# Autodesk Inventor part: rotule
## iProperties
Shininess: 64.0
Length Units: 11269
Angle Units: 11279
Time Units: 11290
Mass Units: 11283
Length Display Precision: 3
Angle Display Precision: 2
Compacted: True
Part Number: rotule
Document SubType Name: Modeling
Created: 2004-06
Material: Par défaut
Designer: David
Density: 0.0
Volumn: 0.0
Area: 0.0
PropertySet Name: Model Information
Control State: 0
Master: False
Checked Out: False
Author: David
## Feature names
1. Révolution1 [Revolution]
2. Chanfrein1 [Chamfer]
3. Chanfrein2 [Chamfer]
